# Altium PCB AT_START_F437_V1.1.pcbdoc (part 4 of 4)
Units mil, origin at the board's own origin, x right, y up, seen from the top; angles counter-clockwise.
Board outline 10746.75 x 3533.35 mil, 2 copper layers (Top Layer, Bottom Layer); 198 components, 235 nets, 885 pads, 1100 vias.
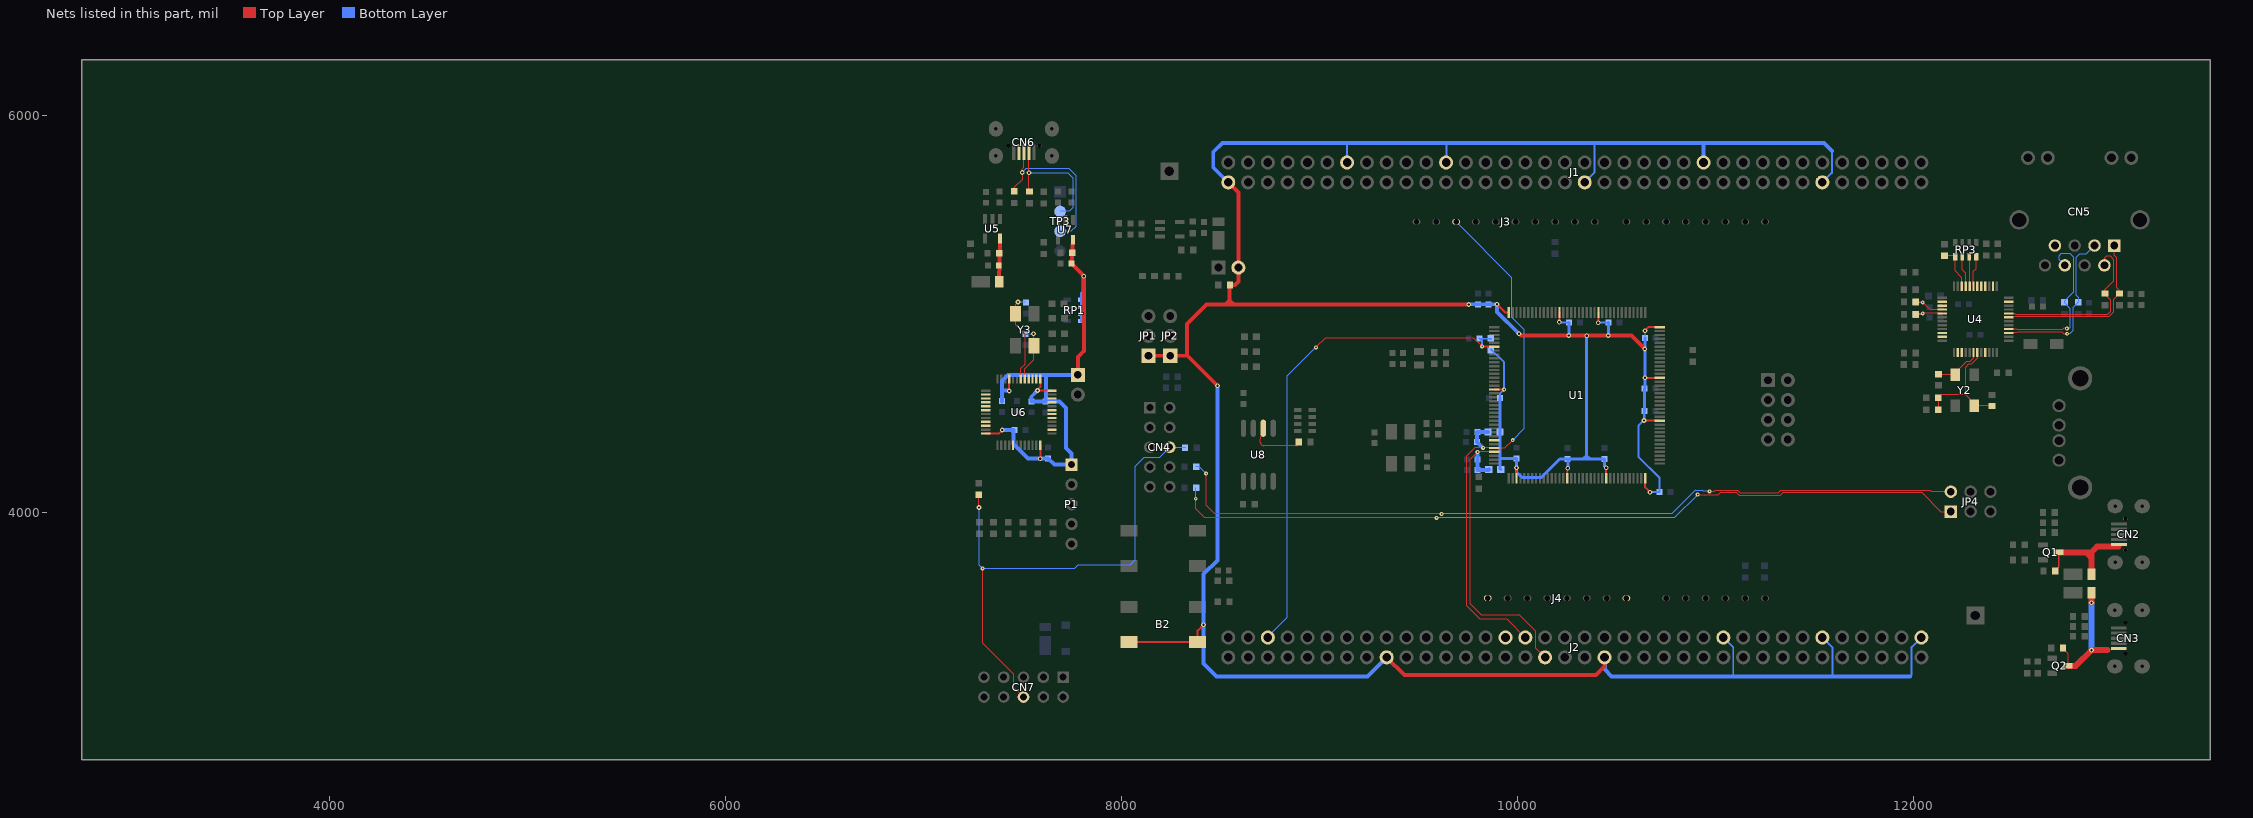
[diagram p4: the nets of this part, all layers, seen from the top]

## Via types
v1: diameter 19.69, hole 7.87, Top Layer to Bottom Layer, 1002 vias
v2: diameter 23.62, hole 11.81, Top Layer to Bottom Layer, 48 vias
v3: diameter 24, hole 12, Top Layer to Bottom Layer, 18 vias
v4: diameter 19.68, hole 7.87, Top Layer to Bottom Layer, 16 vias
v5: diameter 35.43, hole 19.69, Top Layer to Bottom Layer, 12 vias
v6: diameter 27.56, hole 15.75, Top Layer to Bottom Layer, 2 vias
v7: diameter 35.43, hole 19.68, Top Layer to Bottom Layer, 2 vias

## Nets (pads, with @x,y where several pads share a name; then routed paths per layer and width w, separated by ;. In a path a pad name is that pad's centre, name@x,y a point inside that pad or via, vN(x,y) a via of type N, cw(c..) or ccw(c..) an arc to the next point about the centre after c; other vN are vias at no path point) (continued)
QSPI1_SCK: R21.2 U8.6 | length 288.8
  Top Layer w6: 8700.97,4365.6 8700.97,4351.42 ccw(c8716.73,4351.42) 8716.73,4335.66 8879.66,4335.66 ccw(c8879.66,4353.23) R21.2@8897.23,4353.23 ; 8701,4365.56 U8.6@8715.7,4423.06
REF_CLK: R68.2 RP3.5 U4.22 | length 218.5
  Top Layer w6: R68.2@12155.7,5295.86 12202.1,5295.86 12209.5,5288.56 12209.5,5217.66 12242.9,5184.27 U4.22@12242.85,5140.68
RX+: CN5.3 R77.2 U4.3 | length 840.4
  Top Layer w6: U4.3@12479.07,4904.45 12521.53,4904.45 12524.83,4907.75 12751.27,4907.75 12758.37,4900.66 v1(12774.93,4900.66)
  Bottom Layer w6: v1@12774.95,4900.66 12789.11,4900.66 12803.08,4914.63 12803.08,5031.25 12831.79,5059.96 12831.79,5085.31 12819.06,5098.05 12819.06,5284.81 12835.22,5300.97 12867.8,5300.97 CN5.3@12912.8,5345.86
RX-: CN5.6 R76.2 U4.4 | length 846.8
  Top Layer w6: U4.4@12479.07,4924.15 12519.64,4924.15 12524.04,4919.75 12749.11,4919.75 12756.46,4927.1 v1(12773.35,4927.05)
  Bottom Layer w6: R76.2@12761.75,5059.01 12761.75,5067.5 12807.06,5112.8 12807.06,5286.56 12790.3,5303.32 12743.41,5303.32 12732.77,5292.69 12732.77,5276.09 CN5.6@12763.01,5245.86 ; R76.2@12761.8,5056.86 12791.08,5027.58 12791.08,4932.57 12785.62,4927.1 v1(12773.35,4927.05)
RXD0: R65.2 R67.2 U4.29 | length 173.3
  Top Layer w6: R65.2@12010.29,4998.37 12037.93,4998.37 12042.45,5002.89 U4.29@12144.43,5002.89
  Bottom Layer w6: R67.2@12010.68,4997.97 12040.12,4997.97 v4(12045.64,5003.49)
RXD1: R64.2 R66.2 U4.28 | length 186.7
  Top Layer w6: R64.2@12010.29,5062.2 12043.27,5062.2 12082.9,5022.56 U4.28@12144.43,5022.56
  Bottom Layer w6: R66.2@12010.06,5059.71 12044.84,5059.71 v4(12045.81,5058.73)
SWO: CN4.6 CN7.6 R23.1 R52.1 | length 2664.6
  Top Layer w6: v2@7279.8,4023.07 R52.1@7279.8,4080.97 ; v1(7298.75,3715.36) 7298.75,3337.36 7454.76,3181.35 7454.76,3116.23 CN7.6@7505,3065.97
  Bottom Layer w6: v2(7279.77,4023.01) 7279.77,3734.34 7298.74,3715.36 7763.8,3715.36 7781.8,3733.36 8044.8,3733.36 8069.8,3758.36 8069.8,4231.36 8115.8,4277.36 8193.9,4277.36 8244.1,4327.56 8322.3,4327.56 R23.1@8322.3,4325.36
TX+: CN5.1 R79.2 U4.7 | length 899.7
  Top Layer w6: U4.7@12479.07,4983.19 12505.48,4983.19 12509.23,4986.94 12984.96,4986.94 13007.78,5009.77 13007.78,5072.75 13035.7,5100.77 13035.7,5122.47 13022.36,5135.86 13022.36,5286.56 13009.36,5299.56 13009.36,5333.86 13013,5337.5 CN5.1@13013,5345.86
TX-: CN5.2 R78.2 U4.8 | length 906.6
  Top Layer w6: U4.8@12479.07,5002.89 12507.75,5002.89 12511.69,4998.94 12979.99,4998.94 12995.78,5014.74 12995.78,5068.58 R78.2@12965.2,5099.16 ; CN5.2@12963.01,5245.86 12963,5282.57 12971.54,5291.11 12994.39,5291.11 13010.36,5275.14 13010.36,5168 12965.63,5123.27 R78.2@12965.63,5103.28
TXD0: RP3.7 U4.20 | length 148.7
  Top Layer w6: RP3.7@12280.3,5288.56 12282.2,5286.66 U4.20@12282.22,5140.68
TXD1: RP3.8 U4.19 | length 153.7
  Top Layer w6: U4.19@12301.91,5140.68 12301.9,5215.47 12315.8,5229.36 RP3.8@12315.8,5288.56
TXEN: RP3.6 U4.21 | length 155.2
  Top Layer w6: RP3.6@12244.9,5288.56 12244.9,5224.27 12262.5,5206.56 U4.21@12262.54,5140.68
USART1_RX: JP4.2 R24.2 | length 4073.2
  Top Layer w6: v1(8426.75,4194.35) 8426.76,4034.35 8470.75,3990.36 v1(9615.75,3990.36) ; v1(10969.62,4104.78) 10991.69,4104.78 10998.08,4111.17 11111.93,4111.17 11124.63,4098.47 11316.25,4098.47 11328.95,4111.17 12082.58,4111.17 12088.58,4105.17 12185.04,4105.17 JP4.2@12187.47,4102.74
  Bottom Layer w6: R24.2@8375.3,4229.36 8391.7,4229.36 v1(8426.75,4194.35) ; v1(9615.75,3990.36) 10777.76,3990.36 10897.3,4109.9 10932.61,4109.9 10937.73,4104.78 v1(10969.62,4104.78)
USART1_TX: JP4.1 R25.2 | length 4046.4
  Top Layer w6: v1(8374.75,4067.36) 8374.8,4016.86 8421.3,3970.36 v1@9590.7,3970.36 ; v1(10908.55,4088.62) 10938.93,4088.58 10943.22,4084.29 11010.54,4084.29 11025.42,4099.16 11104.97,4099.16 11119.45,4084.68 11325.93,4084.68 11340.42,4099.16 12039.8,4099.16 12136.3,4002.76 JP4.1@12187.5,4002.76
  Bottom Layer w6: R25.2@8374.7,4122.47 8374.7,4067.57 v1(8374.75,4067.36) ; v1(9590.75,3970.36) 10790.28,3970.36 v1(10908.55,4088.62)
USB+: CN6.3 R11.1 TP3.3 | length 860.7
  Top Layer w6: R11.1@7458.2,5618.06 7458.2,5639.31 7497.69,5678.81 v2(7497.69,5715.05) 7497.69,5731.21 7506.7,5740.22 CN6.3@7506.75,5817.59
  Bottom Layer w6: v2(7497.69,5715.05) 7518.66,5736.02 7733.55,5736.02 7767.55,5702.02 7767.55,5441.02 7744.55,5418.02 TP3.3@7689.55,5418.02
USB-: CN6.2 R12.1 TP3.2 | length 659.2
  Top Layer w6: CN6.2@7532.34,5817.59 7532.2,5817.47 v2(7532.2,5713.56) 7532.3,5713.56 7532.3,5619.97 R12.1@7535.2,5617.06
  Bottom Layer w6: v2(7532.2,5713.56) 7729.01,5713.56 7754.55,5688.02 7754.55,5536.01 7736.56,5518.02 TP3.2@7689.55,5518.02
VBAT: C35.1 J2.6 R9.1 U1.6 | length 2722.4
  Top Layer w6: v1@8981.7,4831.36 9030.9,4880.56 9776.5,4880.56 9820.7,4836.36 9821.6,4835.47 U1.6@9881.4,4835.47
  Top Layer w10: v1@9820.7,4836.36 U1.6@9881.4,4835.47
  Bottom Layer w6: J2.6@8738.72,3366.46 8738.7,3370.36 8837.8,3469.47 8837.8,4687.36 v1@8981.7,4831.36 ; C35.1@9808.3,4875.36 9864.3,4875.36 R9.1@9864.8,4874.86
  Bottom Layer w10: v1@9820.7,4836.36 9820.7,4862.86 9808.2,4875.36 R9.1@9864.7,4874.86
  other v1: 8981.75,4831.35 9820.75,4836.35
VBUS1: CN2.1 D2.2 Q1.3 R34.2 | length 562.5
  Top Layer w7.87: R34.2@12712.1,3702.36 12732,3722.26 Q1.3@12731.97,3796.36
  Top Layer w30: Q1.3@12731.97,3796.36 12874.9,3796.36 ; D2.2@12897.7,3686.76 12897.7,3769.14 ; 13034.6,3825.86 12926.6,3825.86 12897.7,3796.97 ; 12874.9,3796.36 12897.7,3796.97 ; 12874.9,3796.36 12897.7,3769.14 ; 12897.7,3769.14 12897.7,3796.97
VBUS2: CN3.1 D6.2 Q2.3 R35.2 | length 623.2
  Top Layer w6: R35.2@12752.3,3313.57 12778.1,3287.66 Q2.3@12778.07,3223.57
  Top Layer w30: Q2.3@12778.07,3223.57 12818.4,3223.57 v3(12897.86,3302.99) ; v3@12897.7,3542.16 D6.2@12897.72,3592.97 ; v3(12897.86,3302.99) 12977.78,3302.99
  Bottom Layer w30: v3@12897.7,3542.16 v3(12897.86,3302.99)
  other v3: 12897.72,3542.14
VCC: C8.1 C9.1 C10.1 C11.1 C12.1 C14.1 J9.1 P1.1 R43.2 RP1.1 RP1.2 RP1.3 RP1.4 U6.1 U6.9 U6.24 U6.36 U6.48 U7.5 | length 2994.1
  Top Layer w10: U6.24@7314.1,4396.47 7380,4396.47 v2(7397.55,4414.02) ; v2(7432.2,4611.56) U6.9@7432.2,4672.06 ; U6.36@7589.71,4337.36 7589.7,4269.27 v2(7589.97,4269.02) ; U6.1@7589.7,4672.06 7589.7,4631.77 7575.2,4617.27 v2(7575.2,4613.56) 7609.3,4613.56 7609.9,4612.97 U6.48@7648.77,4612.97
  Top Layer w20: U7.5@7753.98,5374.91 C14.1@7746.61,5255 7809.3,5192.27 7809.3,4814.47 7779,4784.06 J9.1@7779,4693.06
  Bottom Layer w20: C12.1@7397,4558.97 7397,4613.06 7397,4663.06 7427,4693.06 7618,4693.06 ; 7396.98,4613.02 7430.75,4613.02 v2(7432.2,4611.56) ; v2(7397.55,4414.02) 7455,4413.97 7455,4343.97 7527.9,4271.06 C11.1@7629.2,4271.07 7660.7,4239.56 P1.1@7747.7,4239.56 7747.7,4295.36 7720,4323.06 7720,4525.06 7686,4558.97 7544,4558.97 7544,4582.36 v2(7575.2,4613.56) ; C9.1@7618,4558.97 7618,4693.06 ; J9.1@7779,4693.06 7618,4693.06 ; RP1.4@7800.6,4965.56 7800.6,5103.47 7808.5,5111.47 v2@7808.6,5191.47
  other v2: 7808.56,5191.43
VCC3.5V: C17.1 D5.2 R50.2 U5.5 | length 217
  Top Layer w20: D5.2@7382,5163.56 U5.5@7385.2,5380.57
VDD: B2.1 B2.3 C23.1 C24.1 C25.1 C26.1 C27.1 C28.1 C29.1 C30.1 C31.1 C32.1 C33.1 C34.1 J1.12 J1.23 J1.36 J1.49 J1.59 J1.72 J2.17 J2.39 J2.52 J2.62 J2.72 JP1.1 JP2.1 JP3.2 L1.1 L2.1 R9.2 R17.2 U1.17 U1.39 U1.52 U1.62 U1.72 U1.84 U1.95 U1.108 U1.121 U1.131 U1.144 | length 18405.5
  Top Layer w6: v2(9895.75,5049.35) 9937.4,5007.66 ; v2@10210.7,4959.36 10210.7,5007.27 U1.131@10211.16,5007.69 ; v2(10407.75,4955.35) 10407.8,5007.36 U1.121@10408.01,5007.69 ; v2@10446.7,4223.36 10447.4,4222.66 U1.62@10447.38,4171.06 ; v2(10637.75,4462.35) 10638.7,4461.36 U1.84@10718.05,4461.41 ; v2(10642.75,4916.35) 10660.2,4933.86
  Top Layer w10: B2.3@8037.5,3343.76 B2.1@8384.03,3343.78 8384,3401.57 v2(8413.75,3431.36) ; U1.17@9881.43,4618.9 v1@9931.8,4618.97 ; v2@9895.7,5049.36 9937.4,5007.66 U1.144@9955.2,5007.66 ; U1.39@9994.62,4171.06 v2(9994.63,4224.35) ; v2@10210.7,4959.36 U1.131@10211.16,5007.69 ; U1.52@10250.53,4171.06 10250.5,4218.16 v2(10253.75,4221.35) ; v2(10407.75,4955.35) U1.121@10408.01,5007.69 ; v2@10446.7,4223.36 U1.62@10447.38,4171.06 ; v2(10637.75,4462.35) U1.84@10718,4461.47 ; v2@10642.8,4677.97 U1.95@10718,4677.97 ; v2(10642.75,4916.35) 10660.3,4933.86 U1.108@10718,4933.86 ; U1.72@10644.23,4171.06 10644.2,4124.86 v2(10668.75,4100.35)
  Top Layer w20: JP1.1@8135.8,4789.36 8245.8,4789.36 8331.1,4789.36 ; v2(8484.62,4637.8) 8333.1,4789.36 8331.1,4789.36 ; J1.72@8538.72,5665.03 8589.75,5614.01 JP3.2@8589.75,5234.35 ; JP3.2@8589.75,5234.36 8589.7,5164.36 8571.8,5146.36 8545.3,5146.36 8545.4,5069.66 ; J2.17@9338.72,3266.46 9427.82,3177.35 10394.75,3177.35 10438.72,3221.32 J2.39@10438.72,3266.46 ; v2(9752.75,5048.35) 8566.8,5048.36 ; v2(10006.75,4900.35) 10015.74,4891.36 v2(10257.75,4891.35) ; v2(10257.75,4891.35) v2(10456.75,4891.35) 10574.25,4891.35 v2@10642.25,4823.35 ; 8331.1,4789.36 8331.1,4950.66 8428.8,5048.36 8524.9,5048.36 ; 8524.9,5048.36 8545.4,5069.66 ; 8524.9,5048.36 8566.8,5048.36 ; 8545.4,5069.66 8566.8,5048.36
  Bottom Layer w6: v2@10210.7,4959.36 v2@10211.7,4958.36 ; C32.1@10642.2,4879.36 10642.2,4915.86 v2(10642.75,4916.35) ; v2(10668.75,4100.35) v2@10669.8,4101.36
  Bottom Layer w10: J1.59@9138.72,5765.03 9138.72,5861.57 9140.92,5863.77 ; J1.49@9638.72,5765.03 9641.74,5768.06 9641.74,5863.89 ; R9.2@9864.7,4819.86 9867.6,4819.86 9931.8,4755.66 9931.8,4618.97 9910.3,4597.36 C25.1@9910.3,4576.36 ; v2@10210.7,4958.36 10211.7,4958.36 C34.1@10260.26,4958.36 ; J1.36@10338.72,5665.03 10388.82,5715.13 10388.82,5863.77 ; v2(10407.75,4955.35) 10409.7,4957.36 C33.1@10459.2,4957.36 ; v2(10637.75,4462.35) v2@10637.8,4464.36 ; v2(10668.75,4100.35) 10669.7,4101.36 10669.8,4101.36 C29.1@10716.26,4101.36 10716.3,4172.77 10609.51,4279.56 10609.51,4436.07 v2@10637.8,4464.36 ; J2.52@11038.72,3366.46 11088.75,3316.42 11088.75,3170.36 ; J2.62@11538.72,3366.46 11588.75,3316.42 11588.75,3170.36 ; J1.12@11538.72,5665.03 11586.75,5713.07 11586.75,5823.35 ; 11980.8,3170.36 11989.8,3179.36 11989.8,3317.47 J2.72@12038.72,3366.46 ; v2@10637.8,4464.36 10637.8,4506.86 C30.1@10641.26,4510.36 10641.3,4467.86 v2@10637.8,4464.36
  Bottom Layer w15: C25.1@9910.3,4576.36 L2.1@9911.11,4403.36 9911.1,4269.86 ; L1.1@9915.11,4214.36 9911.1,4218.36 9911.1,4269.86 ; C27.1@10252.8,4268.86 10331.9,4268.86 ; v2(10253.75,4221.35) 10253.8,4266.86 C27.1@10252.75,4267.85 10213.2,4267.86 10119.8,4174.36 10022.8,4174.36 9994.6,4202.47 v2(9994.63,4224.35) C26.1@9994.75,4269.85 9911.1,4269.86 ; v2(10257.75,4891.35) 10260.3,4891.36 C34.1@10260.26,4958.36 ; 10348.2,4285.36 10331.9,4268.86 ; v2(10348.24,4890.35) 10348.24,4285.37 10364.75,4268.86 ; v2(10446.75,4223.35) 10437.8,4232.36 C28.1@10437.75,4268.85 10364.75,4268.86 ; v2@10456.7,4891.36 10459.2,4893.86 C33.1@10459.2,4957.36 ; C30.1@10641.26,4510.36 10641.3,4622.36 C31.1@10640.26,4623.36 10642.2,4625.36 10642.2,4823.35 C32.1@10642.2,4879.36 ; 10331.9,4268.86 10364.75,4268.86
  Bottom Layer w20: v2(8484.62,4637.8) 8484.62,3756.22 8414.8,3686.4 8414.8,3235.36 8479.8,3170.36 9242.6,3170.36 J2.17@9338.72,3266.46 ; J1.72@8538.7,5665.06 8463,5740.77 8463,5817.66 8509.1,5863.77 11546.3,5863.77 11586.8,5823.36 ; v2(9752.75,5048.35) 9753.75,5049.35 9895.7,5049.35 9895.7,5011.36 v2@10006.7,4900.36 ; J2.39@10438.72,3266.46 10440.75,3264.42 10440.75,3204.35 10474.74,3170.36 11980.8,3170.36 ; J1.23@10938.72,5765.03 10938.72,5863.77 10942.09,5863.77
  other v1: 9931.83,4618.94
  other v2: 10642.75,4677.94 10642.25,4823.35 10210.75,4959.35
VDDA: C36.1 C37.1 J2.33 L1.2 U1.33 | length 1704.1
  Top Layer w6: U1.33@9881.4,4303.97 9798.4,4303.97 9757.7,4263.27 9757.7,3539.36 9816.7,3480.36 10009,3480.36 10089.8,3399.57 10089.8,3315.47 J2.33@10138.72,3266.46
  Bottom Layer w6: v1(9797.75,4303.35) 9798.2,4302.86 9798.2,4264.36 9798.2,4212.36 9852.4,4212.36 L1.2@9854.4,4214.36
  Bottom Layer w20: v1(9797.75,4303.35) 9798.2,4264.36 9798.2,4212.36 9852.5,4212.36 L1.2@9854.48,4214.36
VREF+: C38.1 C39.1 J2.32 J3.8 L2.2 U1.32 | length 2959.6
  Top Layer w6: v1@9825.7,4324.36 9880.7,4324.36 U1.32@9881.43,4323.61 ; v1(9975.17,4363.39) 9935.4,4323.56 U1.32@9881.43,4323.61 ; J2.32@10038.72,3366.46 9943.8,3461.36 9809.7,3461.36 9741.1,3529.97 9741.1,4280.66 9784,4323.56 U1.32@9881.43,4323.61
  Bottom Layer w6: J3.8@9689.36,5465.36 9967.8,5186.97 9967.8,4986.47 10031.8,4922.47 10031.8,4419.97 v1(9975.17,4363.39) ; C38.1@9795.3,4354.36 9796.3,4355.36 9796.3,4404.36 L2.2@9850.4,4403.36
  Bottom Layer w20: v1@9825.7,4324.36 9795.3,4354.36 9795.3,4403.36 9796.3,4404.36 L2.2@9850.48,4403.36
  other v1: 9825.75,4324.35
XT1: C50.1 R73.2 R82.1 U4.43 Y2.1 | length 618.5
  Top Layer w6: R82.1@12123.36,4516.51 R73.2@12123.36,4577.58 12140.7,4594.91 12259.18,4594.91 ; U4.43@12321.59,4806.03 12321.59,4776.1 12291.31,4745.81 12275.73,4745.81 12259.18,4729.27 12259.18,4594.91 ; C50.1@12395.11,4536.23 12394.76,4535.87 Y2.1@12304.85,4535.87 12304.85,4549.25 12259.18,4594.91
XT2: C51.1 U4.42 Y2.3 | length 246.7
  Top Layer w6: C51.1@12125.62,4695.76 12207.96,4695.76 Y2.3@12210.37,4693.35 12210.37,4702.91 12266.28,4758.82 12284.01,4758.82 12301.91,4776.72 U4.42@12301.91,4806.03
Y3_1: C20.1 U6.5 Y3.1 | length 287.6
  Top Layer w6: U6.5@7511,4672.06 7511,4723.47 7555.8,4768.27 7555.8,4838.36 7555.6,4838.56 v2@7555.6,4900.06
  Bottom Layer w6: C20.1@7514.6,4900.06 v2@7555.6,4900.06
  other v2: 7555.55,4900.02
Y3_3: C21.2 U6.6 Y3.3 | length 459.6
  Top Layer w6: v2(7477.25,5061.02) 7465.3,5049.06 7465.3,5003.66 7465.3,4946.27 7512.6,4898.97 7512.6,4746.27 7491.3,4725.06 U6.6@7491.3,4672.06
  Bottom Layer w6: v2(7477.25,5061.02) C21.2@7514.6,5060.97
"": CN2.MH1 CN2.MH2 CN3.MH1 CN3.MH2 CN5.7 CN6.4 CN6.MH1 CN6.MH2 J2.30 J4.1 J4.8 U1.30 U4.11 U4.14 U4.16 U4.17 U4.18 U4.26 U4.27 U4.34 U4.35 U4.38 U4.39 U4.45 U6.2 U6.3 U6.4 U6.14 U6.15 U6.16 U6.17 U6.18 U6.21 U6.22 U6.29 U6.38 U6.41 U6.42 U6.43 U6.45 U6.46

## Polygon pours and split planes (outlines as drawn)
GND on Top Layer (solid, remove dead copper, pour order 0): 7142.1,6031.5 13240.53,6031.5 13240.53,3000 7138.16,3000 7138.16,6031.5
GND on Bottom Layer (solid, remove dead copper, pour order 1): 7142.1,6031.5 13240.53,6031.5 13240.53,3000 7138.16,3000 7138.16,6031.5

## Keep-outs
Top Layer:
  region net "": 7636.87,4455.63 7636.87,4434.89 7663.91,4434.89 7663.91,4455.64 7636.94,4455.64
  region net "": 12379.76,4819.13 12379.76,4788.08 12402.13,4788.08 12402.13,4819.1 12380.39,4819.1
  region net "": 12449.09,4968.82 12449.09,4938.09 12455.4,4938.09 12521.19,4938.09 12521.19,4943.86 12521.19,4968.82 12450.27,4968.82
  region net "": 13246.75,5173.35 12478.75,5173.35 12478.75,6033.35 13246.75,6033.35
  region net "": 12901.8,3623.7 12901.8,3653.65 12921.1,3653.65 12921.1,3652.86 12920.71,3623.7
  region net "": 8914.91,4533.05 8937.37,4533.05 8937.37,4527.54 8914.91,4527.54
Bottom Layer:
  region net "": 13246.75,5173.35 12478.75,5173.35 12478.75,6033.35 13246.75,6033.35
Board Outline Layer:
  lines w8 net "": 7792.5,6031.6 cw(c7792.5,5952.86) 7871.24,5952.86 7871.24,5631.02 7910.76,5631.02 7910.76,5952.84 cw(c7989.5,5952.84) 7989.5,6031.58 ; 7792.93,3000 ccw(c7792.93,3078.74) 7871.67,3078.74 7871.7,3078.76 7871.7,3517.97 7910.5,3517.97 7910.5,3078.76 ; 7871.2,5545.97 7871.2,5552.97 7910.8,5552.97 7910.8,5545.97 7910.76,5545.96 7910.76,5224.14 7910.76,4903.35 ; 7871.24,5545.98 7871.24,5224.14 7871.24,4903.87 ; 7989.25,3000 cw(c7989.25,3078.74) 7910.51,3078.74 ; 7871.24,4903.87 7872.11,4903 ; 7871.24,4903.87 ccw(c7872.11,4903.87) 7872.11,4903 ; 7872.11,4903 7910.4,4903 ; 7910.4,4903 7910.76,4903.35 ; 7910.4,4903 ccw(c7910.4,4903.35) 7910.76,4903.35 ; 7910.5,3078.76 7910.51,3078.74 ; 7139.11,3078.74 7139.11,5952.76 cw(c7217.85,5952.76) 7217.85,6031.5 13162.74,6031.5 cw(c13162.74,5952.76) 13241.48,5952.76 13241.48,3078.74 cw(c13162.74,3078.74) 13162.74,3000 7217.85,3000 cw(c7217.85,3078.74) 7139.11,3078.74 ; 7871.11,3606 7871.11,3698 7911.11,3698 7911.11,3606 7871.11,3606 ; 7871.11,3810 7871.11,4809 7871.11,4825 7890.11,4825 7910.11,4825 7910.11,3825 7910.11,3810 7909.11,3810 7871.11,3810

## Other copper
Top Layer:
  drawing of 894 lines, arcs and shapes, not listed
Bottom Layer:
  drawing of 574 lines, arcs and shapes, not listed

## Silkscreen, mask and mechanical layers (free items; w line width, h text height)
Top Silkscreen Layer:
  region net "": 11270.61,5334.24 11232.61,5334.24 11252.61,5354.24 11272.61,5334.24
  region net "": 11132.24,5352.23 11170.24,5352.23 11150.24,5332.23 11130.24,5352.23
  lines w6 net "": 7351.52,3303.99 7351.52,3602.99 ; 7447.92,3303.99 7447.92,3602.99 ; 7544.32,3302.99 7544.32,3602.99 ; 7640.72,3308.99 7640.72,3602.99 ; 11995.82,4351.96 12549.7,4352.4 12549.7,4197.3 11996.6,4196.85 11996.61,4351.97 ; 11996.21,4274.4 12549.71,4274.24 ; 12149.7,4197.3 12151.7,4197.3 12151.7,4352.4 ; 12358.7,4197.3 12358.7,4352.4
  lines w8 net "": 7452.54,3218.01 7452.54,3258.01 7552.54,3258.01 7552.54,3217.01 ; 7743.09,3272.01 7706.09,3235.01 7667.09,3274.01 7743.09,3274.01 ; 8051.66,4557.48 8085.1,4527.56 8050.87,4498.78 8050.87,4557.09 8052.45,4556.69 ; 8091.45,4375.85 8068.6,4375.85 8068.6,4276.56 8091.61,4276.56 8091.61,4277.76
  lines w10 net "": 9862.24,5212.14 11277.94,5212.14 ; 10152.47,3857.56 10605.47,3857.56 ; 10750.71,3857.56 11310.71,3857.56
  text "143" at 8500.63,5936.57 h34.45
  text "133" at 8985.27,5936.57 h34.45
  text "123" at 9490,5936.51 h34.45
  text "113" at 10007.32,5936.59 h34.45
  text "103" at 10493.54,5936.6 h34.45
  text "93" at 11005.36,5936.58 h34.45
  text "83" at 11511.27,5936.6 h34.45
  text "73" at 12006.15,5936.58 h34.45
  text "D8" at 11815.04,5833.35 h34.45 r45
  text "B12" at 12013.26,5833.04 h34.45 r45
  text "D7" at 9519.1,5831.99 h34.45 r45
  text "E0" at 8630.32,5831.23 h34.45 r45
  text "B3" at 9026.83,5830.58 h34.45 r45
  text "D1" at 9925.52,5830.6 h34.45 r45
  text "D10" at 11714.02,5830.95 h34.45 r45
  text "B8" at 8726.71,5830.26 h34.45 r45
  text "B5" at 8928.19,5829.88 h34.45 r45
  text "A13" at 10413.78,5829.53 h34.45 r45
  text "A9" at 10626.26,5830.34 h34.45 r45
  text "D12" at 11614.22,5830.26 h34.45 r45
  text "B14*" at 11913.05,5829.91 h34.45 r45
  text "D5" at 9731.09,5828.92 h34.45 r45
  text "D3" at 9827.04,5829.13 h34.45 r45
  text "A14" at 10216.03,5829.3 h34.45 r45
  text "D14" at 11418.99,5829.3 h34.45 r45
  text "A11*" at 10517.54,5828.49 h34.45 r45
  text "B7" at 8825.4,5826.84 h34.45 r45
  text "G8" at 11020.27,5826.64 h34.45 r45
  text "G10" at 9417.36,5826 h34.45 r45
  text "G2" at 11320.09,5825.89 h34.45 r45
  text "G12" at 9317.45,5824.55 h34.45 r45
  text "GND" at 10313.57,5824.97 h34.45 r45
  text "G6" at 11122.93,5825.01 h34.45 r45
  text "GND" at 8534.03,5823.6 h34.45 r45
  text "C9" at 10719.84,5824.07 h34.45 r45
  text "C7" at 10825.99,5824.37 h34.45 r45
  text "G4" at 11217.53,5824.14 h34.45 r45
  text "GND" at 11511.47,5822.88 h34.45 r45
  text "GND" at 8183.76,5821.73 h40.19
  text "G14" at 9216.47,5822.13 h34.45 r45
  text "C12" at 10017.32,5822.18 h34.45 r45
  text "VDD" at 9617.29,5821.41 h34.45 r45
  text "C10" at 10119.49,5821.46 h34.45 r45
  text "VDD" at 10909.2,5821.38 h34.45 r45
  text "VDD" at 9112.97,5818.14 h34.45 r45
  text "Ethernet" at 12474.73,5604.7 h53.59 r90
  text "B6" at 8942.97,5544.07 h34.45 r45
  text "B9" at 8740.32,5540.54 h34.45 r45
  text "E1" at 8635.96,5537.66 h34.45 r45
  text "B4" at 9036.19,5537.86 h34.45 r45
  text "D6" at 9632.43,5537.66 h34.45 r45
  text "G11" at 9429.96,5533.2 h34.45 r45
  text "G13" at 9310.68,5532.43 h34.45 r30
  text "D4" at 9837.75,5531.57 h34.45 r45
  text "G9" at 9524.62,5531.11 h34.45 r45
  text "D0" at 10039.03,5530.77 h34.45 r45
  text "H2" at 10432.87,5530.14 h34.45 r45
  text "C6" at 10937.92,5529.7 h34.45 r45
  text "G5" at 11231.29,5530.46 h34.45 r45
  text "G3" at 11333.99,5530.29 h34.45 r45
  text "D2" at 9939.43,5529.42 h34.45 r45
  text "C8" at 10833.2,5528.96 h34.45 r45
  text "G7" at 11133.12,5529.47 h34.45 r45
  text "A8*" at 10732.16,5527.33 h34.45 r45
  text "C11" at 10133.43,5525.29 h34.45 r45
  text "A10" at 10628.85,5525.37 h34.45 r45
  text "G15" at 9127.96,5523.59 h34.45 r45
  text "D11" at 11731.46,5522.25 h34.45 r45
  text "A15" at 10224.43,5521.1 h34.45 r45
  text "D15" at 11425.2,5520.64 h34.45 r45
  text "D9" at 11835.19,5520.35 h34.45 r45
  text "GND" at 11019.58,5519.11 h34.45 r45
  text "VDD" at 8516.21,5518.16 h34.45 r45
  text "GND" at 9220.42,5517.51 h34.45 r45
  text "GND" at 9725.67,5517.61 h34.45 r45
  text "A12*" at 10520.9,5516.52 h34.45 r45
  text "B15*" at 11932.97,5515.66 h34.45 r45
  text "D13" at 11626.91,5514.65 h34.45 r45
  text "B13" at 12031.72,5515.05 h34.45 r45
  text "VDD" at 10320.2,5513.34 h34.45 r45
  text "VDD" at 11522.37,5509.32 h34.45 r45
  text "BOOT0" at 8796.87,5488.24 h28.71 r45
  text "4" at 10871.05,5362.3 h45.56 r90
  text "8" at 10410.97,5361.35 h45.56 r90
  text "7" at 10574.05,5361.3 h45.56 r90
  text "2" at 11068.05,5361.3 h45.56 r90
  text "13" at 9913.16,5319.68 h45.94 r90
  text "12" at 10013.16,5319.68 h45.94 r90
  text "#6" at 10670.24,5313.62 h45.94 r90
  text "#5" at 10771.24,5313.62 h45.94 r90
  text "#9" at 10314.16,5312.68 h45.94 r90
  text "#3" at 10970.24,5312.62 h45.94 r90
  text "#11" at 10114.45,5290.83 h45.94 r90
  text "#10" at 10213.81,5284.48 h45.94 r90
  text "GND" at 9814.98,5264.27 h45.94 r90
  text "SCL" at 9509.16,5262.13 h45.94 r90
  text "SDA" at 9609.16,5262.13 h45.94 r90
  text "DIGITAL(#=PWM)" at 10277.85,5246.41 h40.19
  text "RX 0" at 11275.81,5229.22 h45.94 r90
  text "TX 1" at 11172.58,5228.04 h45.94 r90
  text "AREF" at 9713.16,5223.57 h45.94 r90
  text "IDD" at 8675.01,5200.98 h57.42
  text "LD:" at 7789.02,5176.51 h46.73 r270
  text "AT-Link-EZ V1.2" at 7192.01,5077.83 h57.42 r270
  text "1" at 7790.16,5058.65 h47.07 r270
  text "BOOT0" at 7983.24,5059.39 h40.19
  text "BOOT1" at 8205.08,5059.47 h40.19
  text "2" at 7789.37,4994.03 h47.07 r270
  text "GND" at 8309.11,4974.33 h40.19
  text "GND" at 7959.05,4971.36 h40.19
  text "3" at 7788.19,4915.62 h47.07 r270
  text "4" at 7788.98,4841.56 h47.07 r270
  text "VDD" at 8314.44,4773.07 h34.45
  text "VDD" at 7971.41,4763.26 h34.45
  text "OTG1_HOST" at 12771.6,4757.11 h53.59
  text "MISO" at 11060.22,4650.29 h40.19
  text "5V" at 11451.74,4648.32 h40.19
  text "MOSI" at 11432.27,4547.93 h40.19
  text "SCK" at 11075.67,4541.24 h40.19
  text "5V" at 8350.65,4513.11 h40.19
  text "3V3" at 7923.33,4506.07 h40.19
  text "NRST" at 11055.1,4447.93 h40.19
  text "GND" at 11431.58,4442.03 h40.19
  text "BOOT0" at 8323.47,4417.54 h38.94
  text "SWD" at 7930.03,4409.69 h40.19
  text "OTG1" at 12377.34,4379.43 h40.19
  text "USART1" at 11974.56,4377.32 h40.19
  text "NSS" at 11077.64,4348.32 h40.19
  text "PB11" at 11435.02,4343.6 h40.19
  text "SWO" at 8330.72,4311.98 h40.19
  text "SWC" at 7927.07,4306.61 h40.19
  text "ID" at 12426.72,4293.99 h40.19
  text "PA10" at 12201.5,4293.2 h40.19
  text "RX" at 12042.28,4291.25 h40.19
  text "VBUS" at 12377.3,4213.6 h40.19
  text "PA9" at 12210.28,4211.64 h40.19
  text "TX" at 8354.98,4210.52 h40.19
  text "NRST" at 7930.66,4208.49 h40.19
  text "TX" at 12036.16,4205.36 h40.19
  text "GND" at 7952.48,4106.65 h40.19
  text "RX" at 8359.31,4102.17 h40.19
  text "AT-Link" at 8049.26,3997.92 h53.59
  text "AT-START-F437 V1.1" at 10383.26,3899.89 h76.56
  text "POWER" at 10397.07,3794.21 h40.19
  text "ANALOG IN" at 10897.88,3794.2 h40.19
  text "5V" at 10271.16,3645.68 h45.94 r90
  text "IOREF" at 9975.33,3645.4 h45.94 r90
  text "RESET" at 10070.16,3645.02 h45.94 r90
  text "3.3V" at 10171.16,3644.57 h45.94 r90
  text "GND" at 10372.16,3645.13 h45.94 r90
  text "GND" at 10471.45,3645.13 h45.94 r90
  text "AN0" at 10769.24,3642.18 h45.94 r90
  text "AN1" at 10866.17,3642.18 h45.94 r90
  text "AN3" at 11067.11,3640.21 h45.94 r90
  text "AN5" at 11271.2,3640.21 h45.94 r90
  text "AN2" at 10969,3639.02 h45.94 r90
  text "AN4" at 11171.12,3639.02 h45.94 r90
  text "RESET" at 8093,3616.25 h53.59
  text "3V3" at 7660.72,3602.32 h40.19 r270
  text "SWD" at 7571.67,3600.35 h40.19 r270
  text "OTG1" at 12997.43,3599.54 h53.59
  text "SWC" at 7472.78,3597.2 h40.19 r270
  text "NRST" at 7374.67,3596.49 h40.19 r270
  text "GND" at 7286.64,3595.18 h40.19 r270
  text "A2" at 10217,3437.63 h34.45 r45
  text "F0" at 8917.95,3437.4 h34.45 r45
  text "E11" at 11620.33,3436.98 h34.45 r45
  text "BOOT0" at 7571.67,3435.84 h40.19 r270
  text "A0" at 10118.6,3435.71 h34.45 r45
  text "F2" at 9022.73,3434.79 h34.45 r45
  text "A4" at 10422.18,3434.97 h34.45 r45
  text "E9" at 11429.57,3434.97 h34.45 r45
  text "E15" at 11824.26,3435.23 h34.45 r45
  text "E3" at 8517.96,3433.8 h34.45 r45
  text "B0" at 10719.76,3433.61 h34.45 r45
  text "E13" at 11712.95,3434.5 h34.45 r45
  text "F4" at 9122.78,3433.26 h34.45 r45
  text "F6" at 9318.32,3432.26 h34.45 r45
  text "H1*" at 9619.9,3431.51 h34.45 r45
  text "NC" at 9918.24,3432.02 h34.45 r45
  text "B2" at 10820.93,3432.05 h34.45 r45
  text "E5" at 8626.63,3431.46 h34.45 r45
  text "A6" at 10515.67,3430.98 h34.45 r45
  text "F12" at 10918.61,3431.1 h34.45 r45
  text "E7" at 11326.4,3431.09 h34.45 r45
  text "B11" at 11921.98,3430.92 h34.45 r45
  text "SWO" at 7475.93,3429.75 h40.19 r270
  text "F8" at 9421.26,3429.8 h34.45 r45
  text "C2" at 9817.99,3429.72 h34.45 r45
  text "F14" at 11119.18,3430.42 h34.45 r45
  text "F10" at 9516.45,3429.37 h34.45 r45
  text "G0" at 11224.6,3429.06 h34.45 r45
  text "C0" at 9716.68,3426.8 h34.45 r45
  text "C4" at 10616.19,3426.72 h34.45 r45
  text "VDD" at 11507.31,3425.55 h34.45 r45
  text "C14*" at 8807.09,3423.51 h34.45 r45
  text "GND" at 9200.75,3424.28 h34.45 r30
  text "VDD" at 12009.86,3423.9 h34.45 r45
  text "VREF+" at 9976.86,3423.08 h28.71 r30
  text "GND" at 10314.09,3422.73 h34.45 r45
  text "VDD" at 11006.6,3423.39 h34.45 r45
  text "VBAT" at 8702.88,3421.59 h34.45 r45
  text "TX" at 7378.61,3410.75 h40.19 r270
  text "5V" at 7659.93,3407.2 h40.19 r270
  text "RX" at 7285.63,3406.41 h40.19 r270
  text "GND" at 12256.14,3349.38 h40.19
  text "USER" at 8111.32,3232 h53.59
  text "C1" at 9837.23,3143.47 h34.45 r45
  text "G1" at 11337.55,3140.95 h34.45 r45
  text "B1" at 10835.7,3140.42 h34.45 r45
  text "F5" at 9238.62,3138.86 h34.45 r45
  text "C3" at 9937.14,3139.06 h34.45 r45
  text "F1" at 9041.67,3137.81 h34.45 r45
  text "A5" at 10538.6,3136.83 h34.45 r45
  text "F3" at 9136.78,3135.55 h34.45 r45
  text "E2" at 8535.79,3134.94 h34.45 r45
  text "F9" at 9541.55,3134.82 h34.45 r45
  text "A3" at 10334.09,3134.9 h34.45 r45
  text "C5" at 10736.72,3134.98 h34.45 r45
  text "E8" at 11430.29,3134.97 h34.45 r45
  text "E6" at 8737.8,3132.89 h34.45 r45
  text "A1*" at 10236.22,3133.12 h34.45 r45
  text "A7" at 10633.55,3133.41 h34.45 r45
  text "F11" at 10933.96,3133.2 h34.45 r45
  text "E4" at 8632.04,3132.09 h34.45 r45
  text "F7" at 9444.15,3131.06 h34.45 r45
  text "H0*" at 9626.94,3128.58 h34.45 r45
  text "E12" at 11733.46,3128.62 h34.45 r45
  text "H3" at 12038.5,3129.17 h34.45 r45
  text "F13" at 11134.79,3126.33 h34.45 r45
  text "F15" at 11233.27,3126.16 h34.45 r45
  text "E10" at 11637.5,3126 h34.45 r45
  text "E14" at 11838.98,3125.72 h34.45 r45
  text "B10" at 11931.36,3125.98 h34.45 r45
  text "C13" at 8832.38,3122.56 h34.45 r45
  text "GND" at 11019.17,3119.96 h34.45 r45
  text "VDD" at 9321.94,3117.61 h34.45 r45
  text "GND" at 10019.58,3118.12 h34.45 r45
  text "VDD" at 10421.88,3114.52 h34.45 r45
  text "GND" at 11520.32,3114.91 h34.45 r45
  text "C15*" at 8922.22,3111.73 h34.45 r45
  text "NRST" at 9719.25,3089.26 h34.45 r45
  text "VDDA" at 10106.57,3088.37 h34.45 r45
  text "OTG2" at 12992.31,3080.25 h53.59
  text "1" at 8527.53,3068.69 h34.17
  text "11" at 9031.35,3068.53 h34.45
  text "71" at 12027.8,3068.53 h34.45
  text "21" at 9521.12,3068.5 h34.45
  text "31" at 10019.93,3068.5 h34.45
  text "41" at 10515.6,3068.47 h34.45
  text "51" at 11011.27,3068.48 h34.45
  text "61" at 11516.78,3068.48 h34.45
Bottom Silkscreen Layer:
  text "143" at 8595.8,5865.74 h34.45 r45
  text "139" at 8787.8,5864.59 h34.45 r45
  text "135" at 9003.8,5865.16 h34.45 r45
  text "133" at 9107.8,5865.16 h34.45 r45
  text "129" at 9293.13,5864.59 h34.45 r45
  text "125" at 9496.06,5865.16 h34.45 r45
  text "123" at 9596.06,5865.16 h34.45 r45
  text "109" at 10292.13,5864.59 h34.45 r45
  text "105" at 10500.88,5865.16 h34.45 r45
  text "103" at 10593.65,5865.16 h34.45 r45
  text "141" at 8686.47,5862.85 h34.45 r45
  text "137" at 8897.13,5861.69 h34.45 r45
  text "131" at 9201.13,5862.27 h34.45 r45
  text "127" at 9390.47,5861.69 h34.45 r45
  text "121" at 9693.39,5862.27 h34.45 r45
  text "107" at 10393.88,5861.69 h34.45 r45
  text "101" at 10677.98,5862.27 h34.45 r45
  text "115" at 9990.73,5859.96 h34.45 r45
  text "113" at 10095.13,5859.96 h34.45 r45
  text "119" at 9789.39,5859.38 h34.45 r45
  text "95" at 10983.21,5857.58 h34.45 r45
  text "93" at 11085.35,5857.58 h34.45 r45
  text "85" at 11478.85,5857.58 h34.45 r45
  text "83" at 11586.26,5857.58 h34.45 r45
  text "111" at 10183.13,5857.06 h34.45 r45
  text "99" at 10781.35,5857.01 h34.45 r45
  text "89" at 11282.4,5857.01 h34.45 r45
  text "117" at 9890.73,5856.49 h34.45 r45
  text "75" at 11984.31,5855.85 h34.45 r45
  text "73" at 12084.02,5855.85 h34.45 r45
  text "91" at 11176.26,5854.69 h34.45 r45
  text "81" at 11683.11,5854.69 h34.45 r45
  text "79" at 11782.39,5855.27 h34.45 r45
  text "97" at 10877.35,5854.11 h34.45 r45
  text "87" at 11380.78,5854.11 h34.45 r45
  text "77" at 11882.59,5852.38 h34.45 r45
  text "142" at 8690.47,5589.39 h34.45 r45
  text "132" at 9194.47,5588.81 h34.45 r45
  text "122" at 9684.06,5588.81 h34.45 r45
  text "102" at 10696.08,5588.81 h34.45 r45
  text "144" at 8585.72,5587.08 h34.45 r45
  text "140" at 8791.8,5587.08 h34.45 r45
  text "138" at 8893.13,5587.08 h34.45 r45
  text "134" at 9097.13,5586.5 h34.45 r45
  text "130" at 9286.47,5586.5 h34.45 r45
  text "128" at 9391.8,5587.08 h34.45 r45
  text "124" at 9589.39,5586.5 h34.45 r45
  text "120" at 9796.06,5586.5 h34.45 r45
  text "108" at 10391.13,5587.08 h34.45 r45
  text "104" at 10589.32,5586.5 h34.45 r45
  text "100" at 10790.65,5586.5 h34.45 r45
  text "136" at 9001.13,5585.92 h34.45 r45
  text "126" at 9492.06,5585.92 h34.45 r45
  text "106" at 10480.88,5585.92 h34.45 r45
  text "112" at 10182.8,5583.61 h34.45 r45
  text "118" at 9888.06,5581.87 h34.45 r45
  text "116" at 9980.06,5580.71 h34.45 r45
  text "114" at 10082.8,5581.29 h34.45 r45
  text "110" at 10283.13,5581.29 h34.45 r45
  text "92" at 11182.07,5581.23 h34.45 r45
  text "82" at 11686.02,5581.23 h34.45 r45
  text "98" at 10888.17,5579.5 h34.45 r45
  text "94" at 11085.5,5578.92 h34.45 r45
  text "90" at 11288.4,5578.92 h34.45 r45
  text "88" at 11389.83,5579.5 h34.45 r45
  text "84" at 11585.4,5578.92 h34.45 r45
  text "80" at 11787.98,5578.92 h34.45 r45
  text "96" at 10986.83,5578.34 h34.45 r45
  text "86" at 11483.74,5578.34 h34.45 r45
  text "78" at 11888.6,5577.76 h34.45 r45
  text "76" at 11990.17,5576.6 h34.45 r45
  text "74" at 12090.74,5577.18 h34.45 r45
  text "VDD" at 7658.58,4642.64 h34.45 r270
  text "GND" at 7694.12,3824.61 h34.45
  text "AT32F437ZMT7" at 10844.7,3808.32 h150.71
  text "42" at 10589.56,3462.39 h34.45 r45
  text "48" at 10890.28,3460.65 h34.45 r45
  text "40" at 10491.33,3460.07 h34.45 r45
  text "44" at 10686.71,3460.08 h34.45 r45
  text "46" at 10790.28,3459.5 h34.45 r45
  text "22" at 9585.67,3458.34 h34.45 r45
  text "62" at 11588.33,3457.76 h34.45 r45
  text "28" at 9886.15,3456.6 h34.45 r45
  text "32" at 10085.07,3457.18 h34.45 r45
  text "52" at 11086.99,3457.18 h34.45 r45
  text "20" at 9483.31,3456.03 h34.45 r45
  text "24" at 9686.46,3456.02 h34.45 r45
  text "68" at 11883.66,3456.02 h34.45 r45
  text "72" at 12084.66,3456.03 h34.45 r45
  text "26" at 9783.29,3455.45 h34.45 r45
  text "30" at 9987.21,3454.87 h34.45 r45
  text "34" at 10187.92,3454.87 h34.45 r45
  text "38" at 10389.9,3455.45 h34.45 r45
  text "50" at 10986.56,3454.87 h34.45 r45
  text "54" at 11189.99,3454.87 h34.45 r45
  text "58" at 11388.33,3455.45 h34.45 r45
  text "60" at 11487.33,3455.45 h34.45 r45
  text "64" at 11684.66,3455.45 h34.45 r45
  text "66" at 11783.66,3454.87 h34.45 r45
  text "36" at 10287.04,3454.29 h34.45 r45
  text "56" at 11287.99,3454.29 h34.45 r45
  text "70" at 11984.66,3453.71 h34.45 r45
  text "12" at 9077.8,3453.13 h34.45 r45
  text "10" at 8977.4,3450.82 h34.45 r45
  text "14" at 9177.01,3450.82 h34.45 r45
  text "18" at 9380.55,3451.4 h34.45 r45
  text "16" at 9275.43,3450.24 h34.45 r45
  text "4" at 8671.84,3447.32 h34.17 r45
  text "2" at 8570.66,3446.16 h34.17 r45
  text "8" at 8873.02,3443.85 h34.17 r45
  text "6" at 8771.05,3443.27 h34.17 r45
  text "43" at 10687.94,3187.52 h34.45 r45
  text "45" at 10785.08,3187.52 h34.45 r45
  text "49" at 10988.51,3186.94 h34.45 r45
  text "41" at 10582.22,3184.63 h34.45 r45
  text "47" at 10887.94,3184.05 h34.45 r45
  text "23" at 9686.8,3183.47 h34.45 r45
  text "25" at 9785.95,3183.47 h34.45 r45
  text "29" at 9983.44,3182.89 h34.45 r45
  text "63" at 11686.32,3182.89 h34.45 r45
  text "65" at 11793.32,3182.89 h34.45 r45
  text "33" at 10184.16,3182.31 h34.45 r45
  text "35" at 10285.99,3182.31 h34.45 r45
  text "39" at 10488.99,3181.73 h34.45 r45
  text "53" at 11188.65,3182.31 h34.45 r45
  text "55" at 11284.65,3182.31 h34.45 r45
  text "59" at 11485.99,3181.73 h34.45 r45
  text "69" at 11986.32,3182.31 h34.45 r45
  text "21" at 9580.58,3180.58 h34.45 r45
  text "27" at 9889.52,3180 h34.45 r45
  text "61" at 11582.99,3180 h34.45 r45
  text "31" at 10080.58,3179.42 h34.45 r45
  text "37" at 10384.7,3178.84 h34.45 r45
  text "51" at 11078.65,3179.42 h34.45 r45
  text "57" at 11384.99,3178.84 h34.45 r45
  text "67" at 11889.32,3179.42 h34.45 r45
  text "13" at 9178.21,3178.26 h34.45 r45
  text "15" at 9285.56,3178.26 h34.45 r45
  text "19" at 9478.68,3177.69 h34.45 r45
  text "71" at 12081.32,3178.26 h34.45 r45
  text "11" at 9075.85,3175.37 h34.45 r45
  text "17" at 9381.71,3174.79 h34.45 r45
  text "9" at 8970.29,3170.71 h34.17 r45
  text "3" at 8675.01,3170.14 h34.17 r45
  text "5" at 8772.26,3170.14 h34.17 r45
  text "1" at 8564.78,3168.4 h34.17 r45
  text "7" at 8873.05,3165.51 h34.17 r45
Mechanical Layer:
  circle w1 net "": c11349.35,4865.35 r62.99
  circle w1 net "": c9349.35,5465.35 r62.99
  circle w1 net "": c9299.35,3565.36 r62.99
  circle w1 net "": c8027.93,5874.02 r62.99
  circle w1 net "": c8027.93,3157.47 r62.99
  circle w1 net "": c12319.27,3157.47 r62.99
  circle w1 net "": c12319.27,5874.02 r62.99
